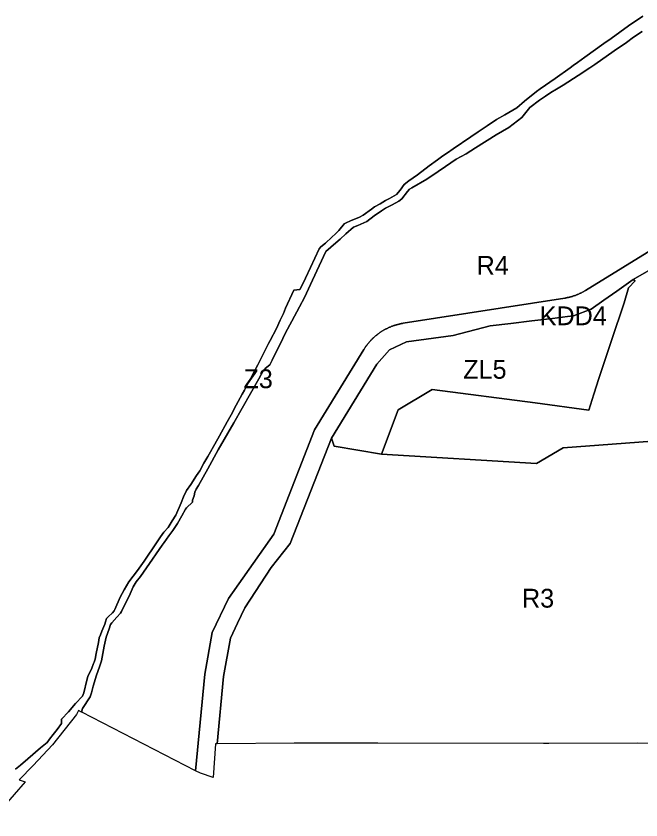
# Model space of a CAD drawing. Extents: x 7439486 to 7443435, y 5551288 to 5554556.
# Drawn here: x 7441056.3 to 7441388.5, y 5552091.6 to 5552519.2 of the extents above; entities that cross this region are included whole.
import ezdxf

# ---------------------------------------------------------------- set-up
doc = ezdxf.new("R2010")
doc.units = 0
doc.layers.add('linie_rozgraniczajace', color=7, linetype='Continuous')
doc.layers.add('oznaczenia_przeznaczen', color=7, linetype='Continuous')

msp = doc.modelspace()

# ---------------------------------------------------------------- linework, layer by layer
at = {"layer": 'linie_rozgraniczajace'}
for points in [[(7441204, 5552373.44), (7441207.21, 5552373.78), (7441208.94, 5552377.15), (7441210.14, 5552379.69), (7441212.77, 5552385.45), (7441217.5, 5552395.28), (7441218.28, 5552396.35), (7441220.73, 5552398.36), (7441224.25, 5552401.62), (7441226.11, 5552403.34), (7441227.87, 5552405.18), (7441229.36, 5552406.94), (7441230.33, 5552408.21), (7441230.69, 5552408.68), (7441231.75, 5552409.26), (7441234.09, 5552410.24), (7441238.95, 5552412.27), (7441240.85, 5552413.19), (7441245.34, 5552416.53), (7441246.84, 5552417.64), (7441249.81, 5552419.34), (7441252.78, 5552421.04), (7441254.78, 5552422.19), (7441258.5, 5552424.2), (7441260.51, 5552426.63), (7441262.65, 5552429.56), (7441265.1, 5552431.5), (7441269.65, 5552434.79), (7441275.88, 5552439.49), (7441280.3, 5552442.65), (7441283.15, 5552444.84), (7441285.58, 5552446.49), (7441288.74, 5552448.56), (7441298.06, 5552454.98), (7441301.95, 5552457.67), (7441306.73, 5552460.8), (7441311.79, 5552464.2), (7441316.21, 5552466.69), (7441322.52, 5552470.43), (7441326.57, 5552473.89), (7441332.94, 5552478.97), (7441334.87, 5552480.5), (7441343, 5552485.94), (7441350.96, 5552491.61), (7441352.49, 5552492.8), (7441354.8, 5552494.4), (7441358.69, 5552497.32), (7441368.7, 5552504.59), (7441372.68, 5552507.32), (7441381.95, 5552513.91), (7441389.56, 5552519.16)], [(7441389.56, 5552519.16), (7441381.95, 5552513.91), (7441372.68, 5552507.32), (7441368.7, 5552504.59), (7441358.69, 5552497.32), (7441354.8, 5552494.4), (7441352.49, 5552492.8), (7441350.96, 5552491.61), (7441343, 5552485.94), (7441334.87, 5552480.5), (7441332.94, 5552478.97), (7441326.57, 5552473.89), (7441322.52, 5552470.43), (7441316.21, 5552466.69), (7441311.79, 5552464.2), (7441306.73, 5552460.8), (7441301.95, 5552457.67), (7441298.06, 5552454.98), (7441288.74, 5552448.56), (7441285.58, 5552446.49), (7441283.15, 5552444.84), (7441280.3, 5552442.65), (7441275.88, 5552439.49), (7441269.65, 5552434.79), (7441265.1, 5552431.5), (7441262.65, 5552429.56), (7441260.51, 5552426.63), (7441258.5, 5552424.2), (7441254.78, 5552422.19), (7441252.78, 5552421.04), (7441249.81, 5552419.34), (7441246.84, 5552417.64), (7441245.34, 5552416.53), (7441240.85, 5552413.19), (7441238.95, 5552412.27), (7441234.09, 5552410.24)], [(7441091.06, 5552149.01), (7441091.67, 5552150.95), (7441095.65, 5552157.06), (7441096.33, 5552159.2), (7441097.27, 5552162.7), (7441099.06, 5552168.59), (7441100.68, 5552172.98), (7441101.68, 5552176.27), (7441103.17, 5552184.01), (7441104.18, 5552188.77), (7441105.82, 5552193.34), (7441106.54, 5552195.54), (7441107.22, 5552196.51), (7441109.9, 5552199.44), (7441111.79, 5552201.65), (7441112.37, 5552202.45), (7441113.58, 5552205.12), (7441116.35, 5552210.65), (7441118.63, 5552215.6), (7441120.19, 5552218.27), (7441122.44, 5552221.11), (7441125.69, 5552225.64), (7441133.98, 5552237.68), (7441135.08, 5552239.1), (7441137.54, 5552242.71), (7441139.65, 5552245.57), (7441142.19, 5552249.27), (7441144.42, 5552253.28), (7441146.29, 5552256.93), (7441146.82, 5552257.68), (7441150.08, 5552260.69), (7441150.1, 5552261.71), (7441150.9, 5552263.98), (7441151.32, 5552266.02), (7441152.02, 5552267.55), (7441153.27, 5552269.54), (7441158.32, 5552278.34), (7441163.7, 5552288.4), (7441172.12, 5552302.81), (7441185.38, 5552326.24), (7441187.82, 5552330.84), (7441188.71, 5552331.77), (7441191.23, 5552333.64), (7441192.5, 5552336.21), (7441198.18, 5552347.69), (7441199.57, 5552350.72), (7441202.87, 5552356.84), (7441207.03, 5552364.56), (7441209.69, 5552369.5), (7441213.94, 5552378.73), (7441220.95, 5552393.95), (7441226.26, 5552398.52), (7441228.57, 5552400.51), (7441231.53, 5552403.29), (7441235.66, 5552406.84), (7441237.92, 5552407.75), (7441241.19, 5552409.21), (7441242.7, 5552409.93), (7441246.66, 5552412.9), (7441250.57, 5552415.63), (7441252.7, 5552416.93), (7441256.19, 5552418.72), (7441259.8, 5552420.75), (7441261.32, 5552421.96), (7441264.4, 5552425.9), (7441265.42, 5552427.12), (7441266.64, 5552427.82), (7441274.7, 5552432.38), (7441280.78, 5552436.5), (7441284.56, 5552439.07), (7441290.32, 5552443.09), (7441295.56, 5552445.89), (7441300.61, 5552449.01), (7441311.59, 5552455.91), (7441318.31, 5552459.88), (7441325.22, 5552465.18), (7441329.37, 5552470.61), (7441334.62, 5552474.35), (7441337.79, 5552476.53), (7441340.68, 5552478.59), (7441343.55, 5552480.25), (7441347.16, 5552482.48), (7441355.09, 5552487.58), (7441361.3, 5552491.61), (7441363.94, 5552493.46), (7441374.24, 5552500.66), (7441380.78, 5552505.16), (7441384.56, 5552507.91), (7441389.11, 5552510.97)], [(7441389.11, 5552510.97), (7441384.56, 5552507.91), (7441380.78, 5552505.16), (7441374.24, 5552500.66), (7441363.94, 5552493.46), (7441361.3, 5552491.61), (7441355.09, 5552487.58), (7441347.16, 5552482.48), (7441343.55, 5552480.25), (7441340.68, 5552478.59), (7441337.79, 5552476.53), (7441334.62, 5552474.35), (7441329.37, 5552470.61), (7441325.22, 5552465.18)], [(7441325.22, 5552465.18), (7441318.31, 5552459.88), (7441311.59, 5552455.91), (7441300.61, 5552449.01), (7441295.56, 5552445.89), (7441290.32, 5552443.09), (7441284.56, 5552439.07), (7441280.78, 5552436.5), (7441274.7, 5552432.38), (7441266.64, 5552427.82), (7441265.42, 5552427.12), (7441264.4, 5552425.9), (7441261.32, 5552421.96), (7441259.8, 5552420.75), (7441256.19, 5552418.72), (7441252.7, 5552416.93), (7441250.57, 5552415.63), (7441246.66, 5552412.9), (7441242.7, 5552409.93), (7441241.19, 5552409.21), (7441237.92, 5552407.75), (7441235.66, 5552406.84), (7441231.53, 5552403.29), (7441228.57, 5552400.51), (7441226.26, 5552398.52), (7441220.95, 5552393.95), (7441213.94, 5552378.73), (7441209.69, 5552369.5), (7441207.03, 5552364.56), (7441202.87, 5552356.84), (7441199.57, 5552350.72), (7441198.18, 5552347.69), (7441192.5, 5552336.21), (7441191.23, 5552333.64), (7441188.71, 5552331.77), (7441187.82, 5552330.84), (7441185.38, 5552326.24), (7441172.12, 5552302.81), (7441163.7, 5552288.4), (7441158.32, 5552278.34), (7441153.27, 5552269.54), (7441152.02, 5552267.55), (7441151.32, 5552266.02), (7441150.9, 5552263.98), (7441150.1, 5552261.71), (7441150.08, 5552260.69), (7441146.82, 5552257.68), (7441146.29, 5552256.93), (7441144.42, 5552253.28), (7441142.19, 5552249.27), (7441139.65, 5552245.57), (7441137.54, 5552242.71), (7441135.08, 5552239.1), (7441133.98, 5552237.68), (7441125.69, 5552225.64), (7441122.44, 5552221.11), (7441120.19, 5552218.27), (7441118.63, 5552215.6), (7441116.35, 5552210.65), (7441113.58, 5552205.12), (7441112.37, 5552202.45), (7441111.79, 5552201.65), (7441109.9, 5552199.44), (7441107.22, 5552196.51), (7441106.54, 5552195.54), (7441105.82, 5552193.34), (7441104.18, 5552188.77), (7441103.17, 5552184.01), (7441101.68, 5552176.27), (7441100.68, 5552172.98), (7441099.06, 5552168.59), (7441097.27, 5552162.7), (7441096.33, 5552159.2), (7441095.65, 5552157.06), (7441091.67, 5552150.95), (7441091.06, 5552149.01), (7441089.39, 5552149.87), (7441088.47, 5552147.69), (7441075.63, 5552131.55), (7441065.43, 5552120.55), (7441057.96, 5552113.03), (7441061.04, 5552111.8), (7441043.46, 5552091.62)], [(7441234.09, 5552410.24), (7441231.75, 5552409.26), (7441230.69, 5552408.68), (7441230.33, 5552408.21), (7441229.36, 5552406.94), (7441227.87, 5552405.18), (7441226.11, 5552403.34), (7441224.25, 5552401.62), (7441220.73, 5552398.36), (7441218.28, 5552396.35), (7441217.5, 5552395.28), (7441212.77, 5552385.45), (7441210.14, 5552379.69), (7441208.94, 5552377.15), (7441207.21, 5552373.78), (7441204, 5552373.44), (7441199.55, 5552363.75), (7441198.4, 5552360.94), (7441196.66, 5552357.37), (7441194.68, 5552353), (7441191.39, 5552346.61), (7441190.56, 5552344.99), (7441186.88, 5552337.85), (7441184.86, 5552333.7), (7441182.58, 5552329.36), (7441180.41, 5552325.24), (7441178.93, 5552322.6), (7441177.72, 5552320.17), (7441176.51, 5552318), (7441173.34, 5552312.3), (7441170.66, 5552307.11), (7441168.59, 5552303.35), (7441164.45, 5552295.86), (7441161.95, 5552291.45), (7441158.97, 5552286.2), (7441158.32, 5552284.95), (7441156.14, 5552281.34), (7441153.92, 5552277.27), (7441152.21, 5552274.72), (7441149.21, 5552269.94), (7441146.98, 5552266.84), (7441145.3, 5552263.41), (7441143.99, 5552260.24), (7441141.26, 5552253.67), (7441139.34, 5552250.68), (7441137.1, 5552247.18), (7441134.82, 5552244.62), (7441133.03, 5552242.16), (7441129.23, 5552236.29), (7441126.24, 5552231.98), (7441124.31, 5552229.25), (7441120.81, 5552224.33), (7441116.3, 5552218.3), (7441113.68, 5552213.98), (7441111.65, 5552210.14), (7441108.81, 5552203.59), (7441108.39, 5552202.75), (7441107.47, 5552201.71), (7441105.24, 5552199.6), (7441104.45, 5552198.7), (7441103.77, 5552197), (7441103.41, 5552195.73), (7441101.95, 5552192.06), (7441101.1, 5552190.07), (7441100.53, 5552188.38), (7441100.06, 5552185.99), (7441098.89, 5552180.09), (7441098.35, 5552177.08), (7441097.74, 5552175.45), (7441097.54, 5552174.73), (7441096.51, 5552172.37), (7441094.4, 5552167.97), (7441093.82, 5552165.99), (7441092.25, 5552159.14), (7441091.54, 5552157.4), (7441087.92, 5552153.57), (7441084.21, 5552149.19), (7441080.48, 5552145.25), (7441080.42, 5552142.99), (7441078.06, 5552139.72), (7441076.04, 5552137.07), (7441074.07, 5552134.49), (7441072.76, 5552132.86), (7441069.28, 5552129.97), (7441062.57, 5552124.1), (7441058.67, 5552120.82), (7441056.02, 5552118.7)], [(7441416.36, 5552408.53), (7441359.09, 5552373.26), (7441358.98, 5552373.18), (7441358.68, 5552373.01), (7441358.38, 5552372.83), (7441358.08, 5552372.66), (7441357.78, 5552372.49), (7441357.47, 5552372.33), (7441357.17, 5552372.16), (7441356.86, 5552372.01), (7441356.55, 5552371.85), (7441356.24, 5552371.7), (7441355.92, 5552371.56), (7441355.61, 5552371.41), (7441355.29, 5552371.27), (7441354.97, 5552371.14), (7441354.65, 5552371), (7441354.33, 5552370.88), (7441354.01, 5552370.75), (7441353.68, 5552370.63), (7441353.36, 5552370.51), (7441353.03, 5552370.4), (7441352.7, 5552370.29), (7441352.37, 5552370.18), (7441352.04, 5552370.08), (7441351.71, 5552369.98), (7441351.38, 5552369.89), (7441351.04, 5552369.8), (7441350.71, 5552369.71), (7441350.37, 5552369.63), (7441350.03, 5552369.55), (7441349.69, 5552369.47), (7441349.35, 5552369.4), (7441349.02, 5552369.34), (7441348.67, 5552369.27), (7441348.33, 5552369.21), (7441347.99, 5552369.16), (7441262.12, 5552355.75), (7441261.77, 5552355.69), (7441261.43, 5552355.63), (7441261.09, 5552355.57), (7441260.75, 5552355.5), (7441260.41, 5552355.43), (7441260.07, 5552355.35), (7441259.74, 5552355.27), (7441259.4, 5552355.19), (7441259.06, 5552355.11), (7441258.73, 5552355.01), (7441258.4, 5552354.92), (7441258.07, 5552354.82), (7441257.73, 5552354.72)], [(7441353.68, 5552370.63), (7441354.01, 5552370.75), (7441354.33, 5552370.88), (7441354.65, 5552371), (7441354.97, 5552371.14), (7441355.29, 5552371.27), (7441355.61, 5552371.41), (7441355.92, 5552371.56), (7441356.24, 5552371.7), (7441356.55, 5552371.85), (7441356.86, 5552372.01), (7441357.17, 5552372.16), (7441357.47, 5552372.33), (7441357.78, 5552372.49), (7441358.08, 5552372.66), (7441358.38, 5552372.83), (7441358.68, 5552373.01), (7441358.98, 5552373.18), (7441359.09, 5552373.26), (7441416.36, 5552408.53)], [(7441428.13, 5552404.2), (7441384.35, 5552379.06), (7441375.71, 5552372.93), (7441368.86, 5552368.09), (7441362.02, 5552363.24), (7441352.71, 5552359.74), (7441349.53, 5552359.42), (7441341.57, 5552358.38), (7441330.43, 5552357.02), (7441319.38, 5552355.67), (7441308.32, 5552354.33), (7441288.62, 5552349.27), (7441263.83, 5552345.87), (7441254.75, 5552341.56), (7441248.17, 5552334.08), (7441223.94, 5552294.61), (7441202.03, 5552238.56), (7441191.9, 5552225.82), (7441177.95, 5552204.48), (7441174, 5552196.22), (7441170.21, 5552188.26), (7441166.55, 5552167.87), (7441163.12, 5552132.05), (7441162.33, 5552132.04), (7441161.15, 5552114.26), (7441154.27, 5552116.45), (7441151.71, 5552117.77)], [(7441056.02, 5552118.7), (7441058.67, 5552120.82), (7441062.57, 5552124.1), (7441069.28, 5552129.97), (7441072.76, 5552132.86), (7441074.07, 5552134.49), (7441076.04, 5552137.07), (7441078.06, 5552139.72), (7441080.42, 5552142.99), (7441080.48, 5552145.25), (7441084.21, 5552149.19), (7441087.92, 5552153.57), (7441091.54, 5552157.4), (7441092.25, 5552159.14), (7441093.82, 5552165.99), (7441094.4, 5552167.97), (7441096.51, 5552172.37), (7441097.54, 5552174.73), (7441097.74, 5552175.45), (7441098.35, 5552177.08), (7441098.89, 5552180.09), (7441100.06, 5552185.99), (7441100.53, 5552188.38), (7441101.1, 5552190.07), (7441101.95, 5552192.06), (7441103.41, 5552195.73), (7441103.77, 5552197), (7441104.45, 5552198.7), (7441105.24, 5552199.6), (7441107.47, 5552201.71), (7441108.39, 5552202.75), (7441108.81, 5552203.59), (7441111.65, 5552210.14), (7441113.68, 5552213.98), (7441116.3, 5552218.3), (7441120.81, 5552224.33), (7441124.31, 5552229.25), (7441126.24, 5552231.98), (7441129.23, 5552236.29), (7441133.03, 5552242.16), (7441134.82, 5552244.62), (7441137.1, 5552247.18), (7441139.34, 5552250.68), (7441141.26, 5552253.67), (7441143.99, 5552260.24), (7441145.3, 5552263.41), (7441146.98, 5552266.84), (7441149.21, 5552269.94), (7441152.21, 5552274.72), (7441153.92, 5552277.27), (7441156.14, 5552281.34), (7441158.32, 5552284.95), (7441158.97, 5552286.2), (7441161.95, 5552291.45), (7441164.45, 5552295.86), (7441168.59, 5552303.35), (7441170.66, 5552307.11), (7441173.34, 5552312.3), (7441176.51, 5552318), (7441177.72, 5552320.17), (7441178.93, 5552322.6), (7441180.41, 5552325.24), (7441182.58, 5552329.36), (7441184.86, 5552333.7), (7441186.88, 5552337.85), (7441190.56, 5552344.99), (7441191.39, 5552346.61), (7441194.68, 5552353), (7441196.66, 5552357.37), (7441198.4, 5552360.94), (7441199.55, 5552363.75), (7441204, 5552373.44)], [(7441151.71, 5552117.77), (7441156.63, 5552169.23), (7441160.6, 5552191.36), (7441169.22, 5552209.4), (7441193.26, 5552243.6), (7441214.95, 5552299.08), (7441241.18, 5552341.8), (7441241.35, 5552342.08), (7441241.54, 5552342.37), (7441241.73, 5552342.66), (7441241.92, 5552342.95), (7441242.11, 5552343.23), (7441242.31, 5552343.52), (7441242.52, 5552343.8), (7441242.72, 5552344.07), (7441242.93, 5552344.35), (7441243.14, 5552344.62), (7441243.36, 5552344.9), (7441243.58, 5552345.16), (7441243.8, 5552345.43), (7441244.02, 5552345.69), (7441244.25, 5552345.96), (7441244.48, 5552346.21), (7441244.72, 5552346.47), (7441244.95, 5552346.72), (7441245.19, 5552346.97), (7441245.43, 5552347.22), (7441245.68, 5552347.46), (7441245.93, 5552347.71), (7441246.18, 5552347.95), (7441246.43, 5552348.18), (7441246.69, 5552348.41), (7441246.95, 5552348.65), (7441247.21, 5552348.87), (7441247.47, 5552349.1), (7441247.74, 5552349.32), (7441248.01, 5552349.53), (7441248.28, 5552349.75), (7441248.55, 5552349.96), (7441248.83, 5552350.17), (7441249.11, 5552350.38), (7441249.39, 5552350.58), (7441249.68, 5552350.78), (7441249.96, 5552350.97), (7441250.25, 5552351.16), (7441250.54, 5552351.35), (7441250.83, 5552351.54), (7441251.13, 5552351.72), (7441251.42, 5552351.9), (7441251.72, 5552352.07), (7441252.02, 5552352.24), (7441252.33, 5552352.41), (7441252.63, 5552352.58), (7441252.94, 5552352.74), (7441253.25, 5552352.9), (7441253.56, 5552353.05), (7441253.87, 5552353.2), (7441254.18, 5552353.35), (7441254.5, 5552353.49), (7441254.81, 5552353.63), (7441255.13, 5552353.77), (7441255.45, 5552353.9), (7441255.78, 5552354.03), (7441256.1, 5552354.15), (7441256.42, 5552354.27), (7441256.75, 5552354.39), (7441257.08, 5552354.5), (7441257.4, 5552354.61), (7441257.73, 5552354.72), (7441258.07, 5552354.82), (7441258.4, 5552354.92), (7441258.73, 5552355.01), (7441259.06, 5552355.11), (7441259.4, 5552355.19), (7441259.74, 5552355.27), (7441260.07, 5552355.35), (7441260.41, 5552355.43), (7441260.75, 5552355.5), (7441261.09, 5552355.57), (7441261.43, 5552355.63), (7441261.77, 5552355.69), (7441262.12, 5552355.75), (7441347.99, 5552369.16), (7441348.33, 5552369.21), (7441348.67, 5552369.27), (7441349.02, 5552369.34), (7441349.35, 5552369.4), (7441349.69, 5552369.47), (7441350.03, 5552369.55), (7441350.37, 5552369.63), (7441350.71, 5552369.71), (7441351.04, 5552369.8), (7441351.38, 5552369.89), (7441351.71, 5552369.98), (7441352.04, 5552370.08), (7441352.37, 5552370.18), (7441352.7, 5552370.29), (7441353.03, 5552370.4), (7441353.36, 5552370.51), (7441353.68, 5552370.63)], [(7441257.73, 5552354.72), (7441257.4, 5552354.61), (7441257.08, 5552354.5), (7441256.75, 5552354.39), (7441256.42, 5552354.27), (7441256.1, 5552354.15), (7441255.78, 5552354.03), (7441255.45, 5552353.9), (7441255.13, 5552353.77), (7441254.81, 5552353.63), (7441254.5, 5552353.49), (7441254.18, 5552353.35), (7441253.87, 5552353.2), (7441253.56, 5552353.05), (7441253.25, 5552352.9), (7441252.94, 5552352.74), (7441252.63, 5552352.58), (7441252.33, 5552352.41), (7441252.02, 5552352.24), (7441251.72, 5552352.07), (7441251.42, 5552351.9), (7441251.13, 5552351.72), (7441250.83, 5552351.54), (7441250.54, 5552351.35), (7441250.25, 5552351.16), (7441249.96, 5552350.97), (7441249.68, 5552350.78), (7441249.39, 5552350.58), (7441249.11, 5552350.38), (7441248.83, 5552350.17), (7441248.55, 5552349.96), (7441248.28, 5552349.75), (7441248.01, 5552349.53), (7441247.74, 5552349.32), (7441247.47, 5552349.1), (7441247.21, 5552348.87), (7441246.95, 5552348.65), (7441246.69, 5552348.41), (7441246.43, 5552348.18), (7441246.18, 5552347.95), (7441245.93, 5552347.71), (7441245.68, 5552347.46), (7441245.43, 5552347.22), (7441245.19, 5552346.97), (7441244.95, 5552346.72), (7441244.72, 5552346.47), (7441244.48, 5552346.21), (7441244.25, 5552345.96), (7441244.02, 5552345.69), (7441243.8, 5552345.43), (7441243.58, 5552345.16), (7441243.36, 5552344.9), (7441243.14, 5552344.62), (7441242.93, 5552344.35), (7441242.72, 5552344.07), (7441242.52, 5552343.8), (7441242.31, 5552343.52), (7441242.11, 5552343.23), (7441241.92, 5552342.95), (7441241.73, 5552342.66), (7441241.54, 5552342.37), (7441241.35, 5552342.08), (7441241.18, 5552341.8), (7441214.95, 5552299.08), (7441193.26, 5552243.6), (7441169.22, 5552209.4), (7441160.6, 5552191.36), (7441156.63, 5552169.23), (7441151.71, 5552117.77), (7441091.17, 5552148.95), (7441091.06, 5552149.01)]]:
    msp.add_lwpolyline(points, dxfattribs=at)
for points in [[(7441250.49, 5552286.2), (7441259.42, 5552309.8), (7441277.55, 5552320.56), (7441332.2, 5552313.39), (7441360.9, 5552309.63), (7441363.5, 5552318.05), (7441366.11, 5552326.46), (7441372.81, 5552346.59), (7441379.51, 5552366.72), (7441381.89, 5552374.63), (7441385.51, 5552378.41), (7441384.35, 5552379.06), (7441428.13, 5552404.2), (7441439.09, 5552405.41), (7441484.76, 5552391.43), (7441500, 5552384.79), (7441507.26, 5552370.92), (7441494.25, 5552318.09), (7441491.57, 5552300.28), (7441347.17, 5552289.52), (7441333.01, 5552281.15)], [(7441223.94, 5552294.61), (7441248.17, 5552334.08), (7441254.75, 5552341.56), (7441263.83, 5552345.87), (7441288.62, 5552349.27), (7441308.32, 5552354.33), (7441319.38, 5552355.67), (7441330.43, 5552357.02), (7441341.57, 5552358.38), (7441349.53, 5552359.42), (7441352.71, 5552359.74), (7441362.02, 5552363.24), (7441368.86, 5552368.09), (7441375.71, 5552372.93), (7441384.35, 5552379.06), (7441385.51, 5552378.41), (7441381.89, 5552374.63), (7441379.51, 5552366.72), (7441372.81, 5552346.59), (7441366.11, 5552326.46), (7441363.5, 5552318.05), (7441360.9, 5552309.63), (7441332.2, 5552313.39), (7441277.55, 5552320.56), (7441259.42, 5552309.8), (7441250.49, 5552286.2), (7441225.43, 5552290.48)], [(7441163.12, 5552132.05), (7441166.55, 5552167.87), (7441170.21, 5552188.26), (7441174, 5552196.22), (7441177.95, 5552204.48), (7441191.9, 5552225.82), (7441202.03, 5552238.56), (7441223.94, 5552294.61), (7441225.43, 5552290.48), (7441250.49, 5552286.2), (7441333.01, 5552281.15), (7441347.17, 5552289.52), (7441491.57, 5552300.28), (7441489.35, 5552285.5), (7441463.15, 5552131.7), (7441427.01, 5552132.17), (7441386.44, 5552132.52), (7441339.55, 5552132.31), (7441336.65, 5552132.29), (7441248.59, 5552132.51), (7441204.07, 5552132.42)]]:
    msp.add_lwpolyline(points, close=True, dxfattribs=at)

# ---------------------------------------------------------------- texts
at = {"layer": 'oznaczenia_przeznaczen'}
for s, p in [('R4', (7441301.19, 5552381.56)), ('KDD4', (7441334.68, 5552354.74)), ('ZL5', (7441294.02, 5552326.28)), ('Z3', (7441177.19, 5552321.24)), ('R3', (7441325.28, 5552204.54))]:
    msp.add_text(s, height=10, dxfattribs=at).set_placement(p)

doc.saveas('drawing.dxf')
